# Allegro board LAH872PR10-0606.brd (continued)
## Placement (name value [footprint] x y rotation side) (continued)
PL4  5A Z150 20M 1210_2P  [5A_Z150_1210_2P]  166.59 45.59 270 bottom
PL301  1.5UH_9A_20%_7X7X3_M  [L_7X7X3_M_2P]  50.77 102.01 270 bottom
PL311  -  [5A_Z80_0805_2P]  45.22 112.96 0 bottom
PL501  1.5UH_9A_20%_7X7X3_M  [L_7X7X3_M_2P]  41.63 101.51 270 bottom
PL511  5A Z150 20M 1210_2P  [5A_Z150_1210_2P]  35.98 114.06 270 bottom
PL1811  5A_Z80_0805_2P  [5A_Z80_0805_2P-NPM]  171.42 56.03 270 bottom
PL1812  1UH_6.6A_20%_5X5X3_M  [L_5X5X3_M_2P]  161.59 54.92 180 bottom
PLB01  4.7UH_5.5A_20%_7X7X3_M  [L_7X7X3_M_2P]  179.96 49.04 180 bottom
PLB02  5A Z150 20M 1210_2P  [5A_Z150_1210_2P]  182.36 55.31 0 bottom
PLH01  1UH_11A_20%_7X7X3_M  [L_7X7X3_M_2P]  158.47 60.82 90 bottom
PLH11  -  [5A_Z80_0805_2P]  163.83 71.82 270 bottom
PLM01  1UH_11A_20%_7X7X3_M  [L_7X7X3_M_2P]  63.53 92.47 90 bottom
PLM11  -  [5A_Z80_0805_2P]  60.33 106.48 0 bottom
PLZ01  HCB3225KF-151T50_2P  [5A_Z150_1210_2P]  158.68 121.68 0 bottom
PLZ02  0.22UH_24A_20%_ 7X7X4_M  [L_7X7X4_M_4P]  157.49 101.58 270 bottom
PLZ04  0.22UH_24A_20%_ 7X7X4_M  [L_7X7X4_M_4P]  148.39 124.78 180 bottom
PQ1  -  [FDV301N-G_SOT23-3]  74.93 147.11 270 top
PQ2  -  [MMST3904-7-F_SOT323-3]  79.53 143.23 0 top
PQ11  -  [2N7002KW_SOT323-3]  193.93 45.94 270 top
PQ12  -  [L2N7002DW1T1G_SC88-6]  174.69 54.41 90 top
PQ13  -  [2N7002KDW_SOT363-6]  174.12 58.8 0 top
PQ801  -  [2N7002KW_SOT323-3]  147.57 43.4 270 top
PQ900  L2N7002DW1T1G 2N SC88-6  [DMN65D8LDW-7_SOT363-6]  170.2 41.34 0 top
PQB03  -  [2N7002KW_SOT323-3]  185.55 66.61 90 top
PQB11  -  [EMB04N03H_EDFN5X6-8-5]  179.46 62.91 90 top
PQB12  -  [AON7506_DFN3X3-8-5]  181.49 64.49 270 top
PQB13  -  [AON7506_DFN3X3-8-5]  176.25 54.16 90 bottom
PQB25  AON7506_DFN33-8-5  [AON7702L_DFN8-5]  185.44 48.57 270 bottom
PQB26  AON7408L_DFN8-5  [AON7702L_DFN8-5]  182.57 50.28 90 bottom
PQB28  -  [LMUN5113T1G_SOT323-3]  190.08 54.8 0 top
PQB29  -  [LTC015EUBFS8TL_UMT3F]  192.13 57.53 180 top
PQB31  2N7002KW_SOT323-3  [DMN65D8LW-7_SOT323-3]  190.41 49.57 0 top
PQB32  -  [RUM002N02GT2L_VMT3]  200.26 55.62 0 top
PQB33  -  [RUM002N02GT2L_VMT3]  196.76 54.94 0 top
PQH01  -  [RUM002N02GT2L_VMT3]  165.9 69.52 180 top
PQM01  -  [AONH36334_DFN3X3A8-10]  61.63 101.26 90 bottom
PQZ01  -  [AON6380_DFN5X6-8-5]  154.97 104.4 180 bottom
PQZ02  AON6314_N_DFN56-8-5  [Q_N_DFN56-8-5]  157.26 109.92 0 bottom
PQZ03  AON6314_N_DFN56-8-5  [Q_N_DFN56-8-5]  161.07 109.92 180 top
PQZ04  -  [AON6380_DFN5X6-8-5]  151.24 122.8 90 bottom
PQZ05  AON6314_N_DFN56-8-5  [Q_N_DFN56-8-5]  148.31 114.48 180 bottom
PQZ06  AON6314_N_DFN56-8-5  [Q_N_DFN56-8-5]  150.34 113.03 90 top
PR1  33_0402_5%  [R_0402]  78.94 148.57 0 top
PR3  100K_0402_1%  [R_0402]  78.94 147.74 0 top
PR4  10K_0402_1%  [R_0402]  81.16 144.6 270 top
PR5  2.2K_0402_5%  [R_0402]  82.44 148.57 0 top
PR6  15K_0402_1%  [R_0402]  79.86 146.28 180 top
PR7  100K_0402_1%  [R_0402]  80.46 142.92 0 top
PR9  16.2K_0402_1%  [R_0402]  52.17 84.65 270 bottom
PR31  0_0402_5%  [R_0402]  175.52 56.73 90 top
PR32  3.3K_1206_5%  [R_1206]  177.44 61.12 270 top
PR33  10K_0402_1%  [R_0402]  170.91 55.32 270 top
PR34  1M_0402_1%  [R_0402]  172.93 61.53 0 top
PR35  0_0402_5%  [R_0402]  173.8 56.8 0 top
PR36  1M_0402_1%  [R_0402]  176.5 56.02 270 top
PR37  100_0402_5%  [R_0402]  163.36 40.01 270 top
PR38  1M_0402_1%  [R_0402]  174.58 61.53 0 top
PR39  200_0402_5%  [R_0402]  164.74 39.24 0 top
PR40  100K_0402_1%  [R_0402]  171.83 56.7 0 top
PR41  10K_0402_1%  [R_0402]  165.65 40.06 180 top
PR42  100_0402_5%  [R_0402]  160.5 40.01 270 top
PR43  100K_0402_1%  [R_0402]  196.82 46.34 90 top
PR44  1M_0402_1%  [R_0402]  175.68 54.15 90 top
PR45  1M_0402_1%  [R_0402]  174.71 57.63 180 top
PR301  0_0603_5%  [R0603_0OHM]  47.6 106.55 270 bottom
PR302  499K_0402_1%  [R_0402]  54.38 110.55 0 bottom
PR303  150K_0402_1%  [R_0402]  54.38 109.66 0 bottom
PR304  10K_0402_1%  [R_0402]  52.29 111.77 270 bottom
PR305  4.7_1206_5%  [R_1206]  49.44 102.55 0 top
PR306  1K_0402_5%  [R_0402]  55.42 106.74 180 bottom
PR501  0_0603_5%  [R0603_0OHM]  37.56 106.04 270 bottom
PR502  0_0402_5%  [R0402_0OHM]  44.29 107.83 270 top
PR503  0_0402_5%  [R0402_0OHM]  42.77 107.83 270 top
PR504  10K_0402_1%  [R_0402]  43.14 109.99 180 bottom
PR505  4.7_1206_5%  [R_1206]  39.34 105.66 270 top
PR506  2.2K_0402_5%  [R_0402]  45.18 107.83 270 top
PR507  0_0402_5%  [R0402_0OHM]  43.73 104.07 180 top
PR508  1M_0402_5%  [R_0402]  46.5 105.97 0 top
PR509  1K_0402_5%  [R_0402]  45.39 106.23 180 bottom
PR801  0_0402_5%  [R0402_0OHM]  150.99 41.71 180 top
PR802  1.33K_0402_1%  [R_0402]  149.64 45.86 270 bottom
PR803  1K_0402_1%  [R_0402]  150.53 44.9 270 bottom
PR901  0_0402_5%  [R_0402]  191.61 54.36 270 top
PR902  200K_0402_1%  [R_0402]  174.02 43.23 90 top
PR903  300K_0402_1%  [R_0402]  173.2 43.23 90 top
PR904  200K_0402_1%  [R_0402]  144.79 83.03 0 top
PR905  100K_0402_1%  [R_0402]  175.12 47.68 180 top
PR906  0_0402_5%  [R_0402]  168.98 48.88 90 top
PR907  237K_0402_1%  [R_0402]  169.83 49.79 270 top
PR908  43.2K_0402_1%  [R_0402]  170.66 49.79 270 top
PR909  14.7K_0402_1%  [R_0402]  173.88 49.46 0 top
PR911  4.32K_0402_1%  [R_0402]  173.07 48.62 90 top
PR1801  0_0402_5%  [R0402_0OHM]  165.02 59.11 180 bottom
PR1802  1M_0402_5%  [R_0402]  164.11 58.35 0 bottom
PR1803  100K_0402_5%  [R_0402]  162.78 58.36 270 bottom
PR1804  4.7_1206_5%  [R_1206]  161.83 55.05 270 top
PR1805  10K_0402_1%  [R_0402]  167.81 57.46 180 bottom
PR1806  20K_0402_1%  [R_0402]  166.9 59.11 0 bottom
PR2501  0_0402_5%  [R0402_0OHM]  59.6 82.69 270 bottom
PR2502  21.5K_0402_1%  [R_0402]  62.21 71.81 180 bottom
PR2503  10K_0402_1%  [R_0402]  61.3 70.92 0 bottom
PR2504  2.2_0402_1%  [R_0402]  65.31 77.71 90 bottom
PRB01  0.01_1206_1%  [R_1206_4P-D]  170.77 50.19 270 bottom
PRB02  0.01_1206_1%  [R_1206_4P-D]  183.1 60.93 270 top
PRB03  3M_0402_5%  [R_0402]  182.6 65.9 90 top
PRB04  1M_0402_1%  [R_0402]  182.6 67.55 90 top
PRB07  4.02K_0402_1%  [R_0402]  192.05 44.36 90 bottom
PRB08  4.02K_0402_1%  [R_0402]  181.83 65.9 90 top
PRB09  374K_0402_1%  [R_0402]  190.71 52.51 0 top
PRB10  52.3K_0402_1%  [R_0402]  191.63 51.62 180 top
PRB11  1_0402_5%  [R_0402]  189.7 52.64 0 bottom
PRB12  2_0402_5%  [R_0402]  189.7 51.75 0 bottom
PRB13  100K_0402_5%  [R_0402]  190.51 49.97 0 bottom
PRB14  0_0603_1%  [R0603_0OHM]  191.21 48.85 180 bottom
PRB15  10_1206_1%  [R_1206]  187.42 54.45 0 bottom
PRB16  47K_0402_1%  [R_0402]  195.46 53.91 90 bottom
PRB17  150K_0402_1%  [R_0402]  194.67 54.95 270 bottom
PRB18  200K_0402_1%  [R_0402]  195.49 53.78 180 top
PRB19  0_0402_5%  [R0402_0OHM]  196.25 54.95 270 bottom
PRB20  0_0402_5%  [R0402_0OHM]  197.04 54.95 270 bottom
PRB21  0_0402_5%  [R0402_0OHM]  197.85 54.69 270 bottom
PRB22  0_0402_5%  [R0402_0OHM]  198.66 53.78 90 bottom
PRB23  100K_0402_1%  [R_0402]  198.97 52.64 0 bottom
PRB24  100K_0402_1%  [R_0402]  198.97 51.77 0 top
PRB25  499K_0402_1%  [R_0402]  193.87 53.91 90 bottom
PRB26  768K_0402_1%  [R_0402]  193.89 55.53 90 bottom
PRB27  200K_0402_1%  [R_0402]  193.76 54.75 270 top
PRB28  100K_0402_1%  [R_0402]  199.88 50.86 180 top
PRB29  0_0402_5%  [R0402_0OHM]  199.88 50.83 180 bottom
PRB30  100_0402_5%  [R_0402]  198.94 49.08 90 top
PRB31  0_0402_5%  [R0402_0OHM]  199.88 49.04 180 bottom
PRB35  100_0402_5%  [R_0402]  199.88 47.3 180 bottom
PRB36  2_0402_5%  [R_0402]  196.76 44.01 270 bottom
PRB37  0_0402_5%  [R0402_0OHM]  197.58 44.01 270 bottom
PRB38  22.6K_0402_1%  [R_0402]  195.25 45.22 270 bottom
PRB39  4.7_0402_5%  [R_0402]  191.22 45.3 270 bottom
PRB40  4.7_1206_5%  [R_1206]  182.61 49.93 270 top
PRB41  0_0603_5%  [R_0603]  188.2 56.85 270 top
PRB42  10K_0402_5%  [R_0402]  198.87 55.79 180 top
PRB43  160K_0402_1%  [R_0402]  198.03 54.67 270 top
PRB44  10K_0402_5%  [R_0402]  194.57 54.67 0 top
PRB45  100K_0402_1%  [R_0402]  189.75 46.59 0 top
PRH01  0_0402_5%  [R0402_0OHM]  165.58 67.66 270 top
PRH02  1M_0402_1%  [R_0402]  166.55 66.74 90 top
PRH03  0_0402_5%  [R_0402]  166.7 59.94 90 bottom
PRH04  0_0402_5%  [R_0402]  167.53 60.85 270 bottom
PRH05  100K_0402_5%  [R_0402]  166.73 63.42 90 top
PRH06  10_0402_1%  [R_0402]  165.55 60.83 180 bottom
PRH07  4.7_1206_5%  [R_1206]  159.76 62.24 90 top
PRH08  5.9K_0402_1%  [R_0402]  167.53 64.18 0 bottom
PRH09  10K_0402_1%  [R_0402]  167.53 63.39 0 bottom
PRH11  2.2_0402_1%  [R_0402]  168.46 61.63 180 bottom
PRH12  1K_0402_1%  [R_0402]  168.44 64.99 180 bottom
PRH13  10_0402_5%  [R_0402]  168.49 65.69 0 top
PRH14  0_0402_5%  [R0402_0OHM]  168.49 64.86 0 top
PRH15  0_0402_5%  [R0402_0OHM]  168.49 64.04 0 top
PRH20  0_0402_5%  [R0402_0OHM]  165.41 71.52 180 top
PRM01  4.7_1206_5%  [R_1206]  63.41 99.82 90 top
PRM02  2.2_0603_5%  [R_0603]  63.15 109.72 270 bottom
PRM03  5K_0402_1%  [R_0402]  67 110.7 0 bottom
PRM04  5.1_0603_5%  [R_0603]  68.22 113.85 180 bottom
PRM05  2.2_0603_5%  [R_0603]  66.82 112.64 0 bottom
PRM06  10K_0402_1%  [R_0402]  65.88 116.98 270 bottom
PRM07  453K_0402_1%  [R_0402]  64.97 116.98 270 bottom
PRM08  0_0402_5%  [R0402_0OHM]  64.16 116.98 270 bottom
PRM09  0_0402_5%  [R0402_0OHM]  61.4 116.98 270 bottom
PRM10  6.04K_0402_1%  [R_0402]  59.93 115.31 180 bottom
PRM11  10K_0402_1%  [R_0402]  59.93 116.96 180 bottom
PRM13  0_0402_5%  [R_0402]  58.14 113.65 90 bottom
PRM14  0_0402_5%  [R0402_0OHM]  59.01 113.66 0 bottom
PRZ00  2K_0402_1%  [R_0402]  156.72 141.97 180 top
PRZ02  10_0402_5%  [R_0402]  155.86 144.57 180 top
PRZ03  2.37K_0402_1%  [R_0402]  154.94 143.71 0 top
PRZ04  47K_0402_1%  [R_0402]  155.8 141.13 270 top
PRZ05  34K_0402_1%  [R_0402]  154.07 141.14 270 top
PRZ06  0_0402_5%  [R0402_0OHM]  154.1 143.71 270 top
PRZ07  301_0402_1%  [R_0402]  154.12 141.98 180 top
PRZ08  2.2_0603_5%  [R_0603]  152.05 137.13 0 top
PRZ09  2.61K_0402_1%  [R_0402]  159.43 139.57 180 top
PRZ10  4.7_1206_5%  [R_1206]  155.1 105.02 90 top
PRZ11  11K_0402_1%  [R_0402]  159.43 140.39 180 top
PRZ12  3.65K_0603_1%  [R_0603]  159.23 138.62 270 top
PRZ13  475_0402_1%  [R_0402]  157.64 143.3 90 top
PRZ15  100_0402_1%  [R_0402]  158.58 143.38 0 top
PRZ16  13.3K_0402_1%  [R_0402]  151.55 144.98 270 top
PRZ18  133K_0402_1%  [R_0402]  150.72 145.04 270 top
PRZ21  100K_0402_1%  [R_0402]  149.07 145.3 270 top
PRZ23  2.2_0402_1%  [R_0402]  148.24 145.61 270 top
PRZ26  1_0603_5%  [R_0603]  148.62 135.31 0 top
PRZ47  2.74K_0402_1%  [R_0402]  142.76 138.07 0 top
PRZ51  10_0402_5%  [R_0402]  139.97 138.89 270 top
PRZ65  2K_0402_1%  [R_0402]  141.04 136.26 90 top
PRZ66  549_0402_1%  [R_0402]  143.46 141.08 270 top
PRZ67  10_0402_5%  [R_0402]  140.36 139.7 0 top
PRZ69  0_0402_5%  [R0402_0OHM]  139.61 140.6 270 top
PRZ70  100K_0402_5%  [R_0402]  143.61 137.55 270 bottom
PRZ71  11K_0402_1%  [R_0402]  141.64 144.66 270 top
PRZ72  100_0402_1%  [R_0402]  143.47 141.92 180 top
PRZ73  301_0402_1%  [R_0402]  141.9 137.17 270 top
PRZ74  4.7_1206_5%  [R_1206]  147.35 119.25 0 top
PRZ75  0_0402_5%  [R0402_0OHM]  140.75 137.97 90 top
PRZ76  133K_0402_1%  [R_0402]  145.58 144.98 270 top
PRZ77  54.9K_0402_1%  [R_0402]  141.01 135.4 0 top
PRZ78  210K_0402_1%  [R_0402]  143.7 135.33 180 top
PRZ79  2.61K_0402_1%  [R_0402]  140.88 144.66 270 top
PRZ80  13.3K_0402_1%  [R_0402]  142.9 143.51 0 top
PRZ81  10K_0402_1%  [R_0402]  142.77 142.74 0 top
PRZ82  2.2_0603_5%  [R_0603]  145.7 136.2 270 top
PRZ84  3.65K_0603_1%  [R_0603]  139.86 144.71 270 top
PRZ85  0_0402_5%  [R_0402]  74.32 130.04 0 top
PRZ86  150K_0402_1%  [R_0402]  152.37 144.06 90 top
PRZ87  150K_0402_1%  [R_0402]  143.81 144.27 180 top
PU301  -  [SY8286BRAC_QFN20_3X3]  49.35 106.73 0 bottom
PU501  -  [SY8288CRAC_QFN20_3X3]  39.31 106.22 0 bottom
PU800  -  [APL5336KAI-TRL_SOP8P8]  147.96 45.76 270 bottom
PU900  -  [AZV3002RL-7_U-FLGA8_1P65X1P65]  171.82 46.18 0 top
PU1801  -  [RT8061AZQW_WDFN10_3X3]  164.24 54.38 90 bottom
PU2501  -  [RT9059GSP_SO8]  59.98 79.85 0 bottom
PUB01  -  [ISL95522HRZ-T_TQFN32_4X4]  196.7 47.8 90 bottom
PUH01  -  [RT6226AGQUF_UQFN12_3X3]  165.1 62.13 90 bottom
PUM01  -  [RT8207PGQW_WQFN20_3X3]  62.05 112.1 90 bottom
PUZ01  ISL62771HRTZ-T_TQFN40_5X5  [ISL62771HRTZ-T_TQFN40_5X5-S]  149.92 142.63 180 top
Q1  L2N7002DW1T1G_SC88-6  [DMN66D0LDW-7_SOT363-6]  126.52 56.6 90 bottom
Q2  AO3416L_SOT23-3  [AO3416_SOT23-3]  133.51 34.25 0 bottom
Q3  ME2301DC-G 1P SOT23-3  [2N7002K_SOT23-3]  109.51 40.85 180 bottom
Q4  AO3416L_SOT23-3  [AO3416_SOT23-3]  104.87 34.96 180 bottom
Q5  L2N7002DW1T1G_SC88-6  [DMN66D0LDW-7_SOT363-6]  114.26 34.76 270 bottom
Q6  -  [2N7002K_SOT23-3]  109.51 35.77 180 bottom
Q7  L2N7002DW1T1G  [DMN66D0LDW-7_SOT363-6]  17.87 122.76 270 bottom
Q8  DDTA144VCA-7-F-GP  [2N7002K_SOT23-3]  11.57 121.22 90 bottom
Q9  DDTA144VCA-7-F-GP  [2N7002K_SOT23-3]  11.57 117.15 90 bottom
Q10  -  [LN2306LT1G_SOT23-3]  54.24 32.95 270 top
Q11  DDTA144VCA-7-F-GP  [2N7002K_SOT23-3]  56.96 29.01 90 top
Q12  -  [2N7002KW_SOT323-3]  20.23 123.28 0 bottom
Q13  -  [LMBT3904LT1G_SOT23-3]  101.89 125.95 180 bottom
Q14  L2N7002DW1T1G  [DMN66D0LDW-7_SOT363-6]  17.87 120.22 270 bottom
Q15  L2N7002DW1T1G_SC88-6  [DMN66D0LDW-7_SOT363-6]  120.28 38.52 270 bottom
Q16  -  [2N7002K_SOT23-3]  152.56 56.98 180 top
Q17  -  [2N7002K_SOT23-3]  148.5 56.98 180 top
Q18  AO3416L_SOT23-3  [AO3416_SOT23-3]  131.09 42.46 270 bottom
Q19  AO3416L_SOT23-3  [AO3416_SOT23-3]  135.79 42.46 270 bottom
Q20  AO3416L_SOT23-3  [AO3416_SOT23-3]  131.07 38.44 270 bottom
Q21  AO3416L_SOT23-3  [AO3416_SOT23-3]  135.71 38.44 270 bottom
QA2  -  [LN2306LT1G_SOT23-3]  41.42 24.61 90 top
QC1  BSS138W 1N SOT-323-3  [MESS138W-G_SOT323-3]  122.14 101.72 0 top
QC2  ME2N7002F1KW-G 2N SOT-363-6  [DMN66D0LDW-7_SOT363-6]  59.84 77.09 0 top
QC3  -  [2N7002K_SOT23-3]  149.61 82.1 270 top
QE1  -  [2N7002K_SOT23-3]  36.27 62.03 270 top
QS1  L2N7002DW1T1G  [DMN66D0LDW-7_SOT363-6]  106.08 42.11 270 bottom
QV1  -  [2N7002K_SOT23-3]  28.36 105.24 0 bottom
QV2  -  [MMBT3904_NL_SOT23-3]  29.88 96.55 180 bottom
QV3  L2N7002DW1T1G  [DMN66D0LDW-7_SOT363-6]  26 99.01 270 bottom
R1  4.7K_0402_5%  [R_0402]  128.88 55.6 180 bottom
R2  2.2K_0402_5%  [R_0402]  126.84 58.6 270 top
R3  2.2K_0402_5%  [R_0402]  124.64 60.76 90 bottom
R4  4.7K_0402_5%  [R_0402]  126.13 55.6 0 bottom
R5  0_0201_5%  [R_0201]  211.39 42.03 0 top
R6  33_0402_5%  [R_0402]  42.58 82.47 90 bottom
R7  0_0603_5%  [R_0603]  215.43 46.99 90 top
R8  0_0402_5%  [R_0402-NPM]  206.08 46.86 0 bottom
R9  0_0402_5%  [R_0402-NPM]  206.08 47.62 0 bottom
R11  0_0201_5%  [R_0201]  208.95 46.9 270 top
R12  0_0201_5%  [R_0201]  209.58 46.9 270 top
R13  0_0603_5%  [R_0603]  218.6 48.38 270 top
R14  0_0603_5%  [R0603_0OHM]  218.6 44.57 90 top
R17  10K_0402_5%  [R_0402]  207.36 48.18 90 top
R19  10K_0402_5%  [R_0402]  206.16 48.18 90 top
R20  0_0603_5%  [R_0603]  219.93 44.64 0 top
R21  4.7K_0402_5%  [R_0402]  115.54 32.84 270 bottom
R22  0_0402_5%  [R_0402]  131.16 33.66 270 bottom
R23  100K_0402_5%  [R_0402]  129.51 33.66 270 bottom
R24  0_0402_5%  [R0402_0OHM]  135.92 34.43 270 bottom
R25  4.7K_0402_5%  [R_0402]  125 33.54 270 bottom
R26  4.7K_0402_5%  [R_0402]  124.11 33.54 270 bottom
R27  0_0603_5%  [R_0603]  112.49 39.86 180 bottom
R28  0_0402_5%  [R_0402]  108.73 44.57 0 bottom
R29  2.2K_0402_5%  [R_0402]  130.34 32.75 90 bottom
R30  51K_0402_5%  [R_0402]  100.49 36.58 270 bottom
R31  100K_0402_5%  [R_0402]  101.38 36.58 270 bottom
R32  100_0603_1%  [R_0603]  111.13 34.92 270 bottom
R33  10K_0402_5%  [R_0402]  113.75 31.94 0 bottom
R34  20K_0402_1%  [R_0402]  54.17 77.3 0 top
R35  10K_0402_5%  [R_0402]  112.95 31.94 180 bottom
R36  0_0402_5%  [R0402_0OHM]  59.72 28.68 90 top
R37  100K_0402_5%  [R_0402]  58.07 31.61 90 top
R38  1K_0402_5%  [R_0402]  60.61 29.6 270 top
R39  0_0402_5%  [R0402_0OHM]  58.07 33.38 90 top
R40  200_0402_5%  [R_0402]  10.94 119.95 0 top
R41  0_0402_5%  [R_0402]  58.96 34.3 270 top
R42  10K_0402_5%  [R_0402]  23.08 123.01 270 bottom
R43  200_0402_5%  [R_0402]  10.94 122.42 0 top
R44  0_0402_5%  [R0402_0OHM]  19.59 120.15 270 bottom
R45  18.7K_0402_1%  [R_0402]  181.09 66.54 180 bottom
R46  2K_0402_1%  [R_0402]  176.75 68.02 270 bottom
R47  0_0603_5%  [R0603_0OHM]  218.98 27.74 180 top
R48  0_0603_5%  [R_0603]  215.17 27.74 0 top
R49  100K_0402_5%  [R_0402]  17.48 117.79 0 bottom
R50  100K_0402_5%  [R_0402]  16.68 117.79 180 bottom
R51  0_0402_5%  [R_0402]  33.09 61.68 270 top
R52  20K_0402_5%  [R_0402]  154.14 44.25 0 top
R53  0_0402_5%  [R_0402]  32.33 61.68 270 top
R54  1K_0402_5%  [R_0402]  142.6 40.44 180 bottom
R55  100K_0402_5%  [R_0402]  121.26 37.62 0 bottom
R56  470_0603_5%  [R_0603]  154.21 59.18 270 top
R57  100K_0402_5%  [R_0402]  117.3 37.01 180 bottom
R58  4.7K_0402_5%  [R_0402]  147.66 58.73 0 top
R59  1K_0402_5%  [R_0402]  133.63 35.9 0 bottom
R60  100K_0402_5%  [R_0402]  122.18 38.53 180 bottom
R61  0_0402_5%  [R0402_0OHM]  124.09 36.62 270 bottom
R63  10K_0402_5%  [R_0402]  115.57 37.87 270 bottom
R64  0_0402_5%  [R_0402]  125.54 43.19 270 bottom
R65  0_0402_5%  [R0402_0OHM]  116.38 37.87 0 bottom
R66  0_0201_5%  [R_0201]  126.72 36.36 0 bottom
R67  0_0201_5%  [R_0201]  126.05 36.35 270 bottom
R68  0_0402_5%  [R_0402]  126.37 43.19 270 bottom
R71  0_0402_5%  [R_0402]  131.8 44.77 270 bottom
R72  0_0402_5%  [R_0402]  131.62 35.14 90 bottom
R73  0_0402_5%  [R_0402]  140.12 37.83 90 bottom
R78  100K_0402_5%  [R_0402]  19.27 123.76 180 bottom
RA1  0_0805_5%  [R0805_0OHM]  37.65 7.23 180 top
RA8  100K_0402_5%  [R_0402]  35.42 9.14 180 top
RA30  0_0402_5%  [R_0402]  36.43 13.65 180 top
RA31  1K_0402_5%  [R_0402]  36.43 17.97 180 top
RA32  0_0402_5%  [R_0402]  36.43 16.44 180 top
RA33  0_0402_5%  [R0402_0OHM]  39.02 8.56 90 top
RA34  0_0603_5%  [R0603_0OHM]  26.83 20.12 90 top
RA35  0_0402_5%  [R0402_0OHM]  34.72 20.57 180 top
RA36  0_0402_5%  [R0402_0OHM]  36.41 20 0 top
RA37  0_0402_5%  [R0402_0OHM]  30.51 20.43 90 top
RA38  0_0402_5%  [R_0402]  21.69 9.22 270 top
RA39  0_0402_5%  [R_0402]  26.96 8.01 270 top
RA40  100K_0402_5%  [R_0402]  33.74 17.97 0 top
RA41  0_0402_5%  [R_0402]  29.69 20.43 90 top
RA46  33_0402_5%  [R_0402]  36.75 10.41 180 top
RA47  100K_0402_5%  [R_0402]  26.12 16.82 0 top
RA48  10K_0402_5%  [R_0402]  35.52 17.2 0 top
RA50  33_0402_5%  [R_0402]  37.7 12.19 180 top
RA51  200K_0402_1%  [R_0402]  32.91 19.74 0 top
RA52  4.7K_0402_5%  [R_0402]  21.8 13.77 0 top
RA53  4.7K_0402_5%  [R_0402]  21.8 12.25 0 top
RA54  10K_0402_5%  [R_0402]  17.18 11.98 90 bottom
RA55  1K_0402_5%  [R_0402]  23.96 13.56 0 top
RA56  2.2K_0402_5%  [R_0402]  19.41 13.97 180 top
RA57  10K_0402_5%  [R_0402]  18.13 10.35 270 bottom
RA58  10_0402_1%  [R_0402]  24.88 14.89 180 top
RA59  1K_0402_5%  [R_0402]  23.96 15.67 0 top
RA60  2.2K_0402_5%  [R_0402]  20.35 13.98 90 top
RA61  10_0402_1%  [R_0402]  24.88 12.8 180 top
RA62  0_0402_5%  [R0402_0OHM]  16.09 15.55 0 top
RA63  0_0805_5%  [R_0805]  23.97 19.08 90 top
RA65  0_0402_5%  [R0402_0OHM]  39.16 15.3 180 top
RC1  196_0402_1%  [R_0402]  145.71 81.26 180 top
RC2  196_0402_1%  [R_0402]  144.79 79.29 0 top
RC3  0_0402_5%  [R0402_0OHM]  105.11 79.88 0 top
RC4  39.2_0402_1%  [R_0402]  106.01 79.05 270 top
RC5  1K_0402_1%  [R_0402]  105.12 79.05 270 top
RC6  1K_0402_5%  [R_0402]  106.08 81.67 270 top
RC7  1K_0402_1%  [R_0402]  103.28 80.76 270 top
RC8  2.2K_0402_5%  [R_0402]  123.8 101.14 90 top
RC9  0_0402_5%  [R0402_0OHM]  138.67 143 180 top
RC10  0_0402_5%  [R0402_0OHM]  123.73 92.25 270 top
RC11  1K_0402_5%  [R_0402]  115.03 140.44 90 top
RC12  0_0402_5%  [R0402_0OHM]  122.71 92.25 270 top
RC13  150_0402_1%  [R_0402]  125.64 90.15 180 top
RC14  1K_0402_5%  [R_0402]  116.68 140.44 90 top
RC15  2K_0402_1%  [R_0402]  125.64 90.97 180 top
RC16  1K_0402_5%  [R_0402]  115.86 140.44 90 top
RC17  300_0402_5%  [R_0402]  118.39 97.84 270 top
RC18  300_0402_5%  [R_0402]  119.72 94.15 90 top
RC19  4.7K_0402_5%  [R_0402]  124.36 105.5 90 top
RC20  4.7K_0402_5%  [R_0402]  123.47 105.5 90 top
RC21  0_0402_5%  [R0402_0OHM]  124.36 103.79 90 top
RC22  100K_0402_5%  [R_0402]  152.36 81.08 0 bottom
RC23  0_0402_5%  [R_0402]  123.47 104.7 270 top
RC24  1K_0402_5%  [R_0402]  123.73 92.99 90 top
RC25  1K_0402_5%  [R_0402]  119.88 92.38 90 top
RC26  4.7K_0402_5%  [R_0402]  131.99 39.19 90 top
RC27  1K_0402_5%  [R_0402]  119.88 91.26 270 top
RC28  1K_0402_5%  [R_0402]  124.19 88.77 180 top
RC29  0_0402_5%  [R0402_0OHM]  118.99 90.35 90 top
RC30  0_0402_5%  [R_0402]  118.03 90.35 90 top
RC31  0_0402_5%  [R_0402]  124.07 74.43 270 top
RC32  0_0402_5%  [R_0402]  131.98 40.91 90 top
RC33  1K_0402_5%  [R_0402]  119.05 97.99 270 bottom
RC34  10K_0402_5%  [R_0402]  144.53 71.67 0 bottom
RC35  10K_0402_5%  [R_0402]  120.54 58.59 0 top
RC36  10K_0402_5%  [R_0402]  104.76 57.06 180 top
RC37  0_0402_5%  [R_0402]  131.66 61.39 270 bottom
RC38  0_0402_5%  [R_0402]  47.07 29.81 180 bottom
RC39  0_0402_5%  [R0402_0OHM]  30.37 69.92 90 top
RC40  0_0402_5%  [R0402_0OHM]  33.69 68.5 90 top
RC41  15K_0402_5%  [R_0402]  143.19 77.21 180 bottom
RC42  10K_0402_5%  [R_0402]  151.55 81.01 90 bottom
RC43  15K_0402_5%  [R_0402]  143.19 78.23 180 bottom
RC44  10K_0402_5%  [R_0402]  43.01 86.97 270 top
RC45  15K_0402_5%  [R_0402]  142.21 74.67 270 bottom
RC48  4.7K_0402_5%  [R_0402]  148.25 79.22 180 bottom
RC49  100K_0402_5%  [R_0402]  143.18 79.03 180 bottom
RC50  0_0402_5%  [R_0402]  147.08 69.57 0 top
RC51  0_0402_5%  [R_0402]  144.5 72.71 0 bottom
RC52  0_0402_5%  [R0402_0OHM]  152.36 81.85 0 bottom
RC53  10K_0402_5%  [R_0402]  119.81 60.76 90 bottom
RC54  0_0402_5%  [R0402_0OHM]  46.15 28.93 0 bottom
RC55  10K_0402_5%  [R_0402]  147.02 72.43 0 top
RC56  10K_0402_5%  [R_0402]  120.83 61.67 270 bottom
RC57  10K_0402_5%  [R_0402]  118.76 57.76 0 top
RC59  10K_0402_5%  [R_0402]  104.16 47.11 0 top
RC60  10K_0402_5%  [R_0402]  144.79 72.43 0 top
RC61  10K_0402_5%  [R_0402]  120.95 63.8 90 bottom
RC62  22 +-5% 0402  [R_0402]  147.99 71.38 270 top
RC63  33_0402_5%  [R_0402]  144.85 78.21 0 top
RC65  8.2K_0402_5%  [R_0402]  99.25 43.76 180 top
RC66  0_0402_5%  [R_0402]  100.3 47.1 90 top
RC67  0_0402_5%  [R0402_0OHM]  100.3 45.19 90 top
RC68  100K_0402_5%  [R_0402]  150.78 81.01 90 bottom
RC69  100K_0402_5%  [R_0402]  145.41 75.94 180 bottom
RC70  10K_0402_5%  [R_0402]  145.79 77.06 180 top
RC71  1K_0402_5%  [R_0402]  145.41 78.23 180 bottom
RC72  2.2K_0402_5%  [R_0402]  145.41 77.21 180 bottom
RC73  2.2K_0402_5%  [R_0402]  145.41 73.72 180 bottom
RC74  10K_0402_5%  [R_0402]  148.25 80.05 180 bottom
RC75  10K_0402_5%  [R_0402]  119.37 74.24 270 top
RC76  10K_0402_5%  [R_0402]  121.06 49.71 270 bottom
RC77  10K_0402_5%  [R_0402]  118.7 51.86 0 bottom
RC78  10K_0402_5%  [R_0402]  118.58 49.71 270 bottom
RC79  10K_0402_5%  [R_0402]  144.81 74.4 0 top
RC80  10K_0402_5%  [R_0402]  144.79 71.35 0 top
RC81  10K_0402_5%  [R_0402]  140.84 77.21 180 bottom
RC82  10K_0402_5%  [R_0402]  144.81 73.45 0 top
RC83  10K_0402_5%  [R_0402]  145.16 61.26 180 bottom
RC84  10K_0402_5%  [R_0402]  119.67 57 180 top
RC85  10K_0402_5%  [R_0402]  133.43 67.39 270 top
RC86  10K_0402_5%  [R_0402]  145.16 60.32 180 bottom
RC87  10K_0402_5%  [R_0402]  132.61 67.39 270 top
RC88  2K_0402_5%  [R_0402]  120.23 48.79 90 bottom
RC89  2K_0402_5%  [R_0402]  120.93 51.86 270 bottom
RC90  2K_0402_5%  [R_0402]  147.04 74.42 0 top
RC91  2K_0402_5%  [R_0402]  147.09 71.36 270 top
RC92  2.2K_0402_5%  [R_0402]  143.19 75.94 180 bottom
RC93  0_0402_5%  [R0402_0OHM]  157.21 75.37 180 bottom
RC94  2K_0402_5%  [R_0402]  119.41 48.79 90 bottom
RC95  2.2K_0402_5%  [R_0402]  147.04 73.4 0 top
RC96  22K_0402_5%  [R_0402]  144.85 75.92 0 top
RC97  20M_0402_5%  [R_0402]  145.21 64.97 270 bottom
RC98  10K_0402_5%  [R_0402]  148.25 81.13 180 bottom
RC99  10K_0402_5%  [R_0402]  103.85 57.95 0 top
RC100  11.8K_0402_1%  [R_0402]  132.89 73.34 180 top
RC101  10K_0402_5%  [R_0402]  121.45 59.41 180 top
RC102  1K_0402_1%  [R_0402]  129.98 71.82 225 top
RC103  1K_0402_1%  [R_0402]  130.05 72.83 180 top
RC104  10K_0402_5%  [R_0402]  121.34 64.94 180 top
RC105  1K_0402_1%  [R_0402]  144.79 80.24 0 top
RC106  1K_0402_1%  [R_0402]  144.79 82.14 0 top
RC107  33_0402_5%  [R_0402]  122.9 60.28 90 bottom
RC108  10K_0402_5%  [R_0402]  145.72 80.24 180 bottom
RC109  33_0402_5%  [R_0402]  123.73 60.28 90 bottom
RC110  33_0402_5%  [R_0402]  130.84 60.48 90 bottom
RC111  33_0402_5%  [R_0402]  101.25 48.03 270 top
RC112  100K_0402_5%  [R_0402]  99.16 49.79 270 top
RC113  10K_0402_5%  [R_0402]  32.22 81.47 0 top
RC114  10K_0402_5%  [R_0402]  129.25 60.31 270 bottom
RC115  10K_0402_5%  [R_0402]  126.39 62.47 270 bottom
RC116  1M_0402_5%  [R_0402]  141.11 88.8 90 bottom
RC117  0_0603_5%  [R_0603]  131.66 62.33 180 top
RC118  0_0603_5%  [R0603_0OHM]  128.81 63.6 0 top
RC119  10K_0402_5%  [R_0402]  131.92 48.63 270 bottom
RC120  10K_0402_5%  [R_0402]  128.35 62.21 0 top
RC121  10K_0402_5%  [R_0402]  129.25 60.48 90 top
RC122  0_0402_5%  [R0402_0OHM]  122.77 64.97 90 top
RC123  0_0402_5%  [R0402_0OHM]  133.99 60.53 90 top
RC124  1K_0402_5%  [R_0402]  148.49 62.16 270 top
RC125  1K_0402_5%  [R_0402]  204.83 37.78 180 top
RC126  10M_0402_5%  [R_0402]  153.45 80.75 90 top
RC127  0_0402_5%  [R_0402]  156.29 74.48 0 bottom
RC128  10_0402_5%  [R_0402]  131.85 50.98 270 bottom
RC130  10K_0402_5%  [R_0402]  31.9 85.28 0 top
RC131  10K_0402_5%  [R_0402]  25.62 90.94 270 top
RC132  10K_0402_5%  [R_0402]  156.23 78.04 0 bottom
RC133  10K_0402_5%  [R_0402]  157.15 78.99 180 bottom
RD1  1K_0402_1%  [R_0402]  71.39 83.66 180 top
RD2  1K_0402_1%  [R_0402]  71.45 69.57 180 top
RD3  1K_0402_1%  [R_0402]  70.54 68.74 0 top
RD4  0_0402_5%  [R0402_0OHM]  79.58 76.74 180 top
RD5  1K_0402_1%  [R_0402]  74.39 47.32 270 top
RD6  1K_0402_1%  [R_0402]  75.35 46.4 90 top
RE2  0_0603_5%  [R_0603]  43.21 89.4 270 top
RE3  0_0603_5%  [R_0603]  29.05 76.39 0 top
RE5  100K_0402_1%  [R_0402]  54.29 69.35 0 top
RE6  0_0402_5%  [R0402_0OHM]  43.77 86.97 270 top
RE7  0_0603_5%  [R_0603]  29.05 72.96 0 top
RE8  0_0603_5%  [R0603_0OHM]  32.99 72.9 180 top
RE9  0_0402_1%  [R_0402]  55.2 68.33 180 top
RE10  2.2K_0402_5%  [R_0402]  57.9 79.88 180 top
RE11  33_0402_5%  [R_0402]  33.13 77.15 180 top
RE12  0_0402_5%  [R_0402]  41.64 66.04 180 top
RE13  2.2K_0402_5%  [R_0402]  55.02 74.45 180 top
RE14  2.2K_0402_5%  [R_0402]  55.02 75.27 180 top
RE15  2.2K_0402_5%  [R_0402]  56.88 75.94 180 top
RE16  100K_0402_5%  [R_0402]  201.85 43.24 180 bottom
RE17  10K_0402_5%  [R_0402]  32.8 71.21 180 top
RE18  100K_0402_5%  [R_0402]  42.25 86.05 90 top
RE19  10K_0402_5%  [R_0402]  31.96 75.12 0 top
RE20  0_0402_5%  [R0402_0OHM]  52.6 86.16 90 top
RE21  10K_0402_5%  [R_0402]  31.96 74.33 0 top
RE23  10K_0402_5%  [R_0402]  42.08 81.02 180 bottom
RE24  10K_0402_5%  [R_0402]  54.59 84.64 180 top
RE25  10K_0402_5%  [R_0402]  55.69 80.48 90 top
RE26  100K_0402_5%  [R_0402]  136.75 34.43 270 bottom
RE28  100K_0402_5%  [R_0402]  50.94 86.16 90 top
RE29  100K_0402_5%  [R_0402]  38.32 67.29 90 bottom
RE30  0_0402_5%  [R0402_0OHM]  47.28 86.09 90 top
RE31  0_0402_5%  [R0402_0OHM]  32.22 79.81 0 top
RE32  0_0402_5%  [R0402_0OHM]  32.8 70.32 180 top
RE33  0_0402_5%  [R0402_0OHM]  48.22 88.32 0 top
RE34  0_0402_5%  [R_0402]  40.29 88.53 270 top
RE35  0_0402_5%  [R0402_0OHM]  40.12 83.24 180 bottom
RE36  0_0402_5%  [R_0402]  36.28 81.02 270 bottom
RE37  0_0402_5%  [R0402_0OHM]  44.74 88.37 90 top
RE38  100K_0402_5%  [R_0402]  32.8 69.43 180 top
RE39  10K_0402_5%  [R_0402]  53.91 71.08 0 top
RE41  6.8K_0402_5%  [R_0402]  54.82 71.89 180 top
RE43  240_0402_1%  [R_0402]  58.82 36 0 bottom
RE44  100K_0402_5%  [R_0402]  222.87 64.75 180 top
RE47  100K_0402_5%  [R_0402]  29.55 75.12 0 top
RE48  0_0402_5%  [R0402_0OHM]  56.1 72.4 270 top
RE49  100K_0402_5%  [R_0402]  43.16 27.74 180 bottom
RE50  47K_0402_5%  [R_0402]  38.12 65.91 0 top
RE51  10K_0402_5%  [R_0402]  35.07 72.39 0 bottom
RE52  10K_0402_5%  [R_0402]  35.07 71.56 0 bottom
RE53  0_0402_5%  [R_0402]  54.69 80.49 90 top
RE54  100K_0402_5%  [R_0402]  56.71 79.88 0 bottom
RH1  33_0402_5%  [R_0402]  91.16 135.07 270 bottom
RH2  10K_0402_5%  [R_0402]  92.25 135.03 270 bottom
RH3  10K_0402_5%  [R_0402]  93.14 135.03 270 bottom
RH4  10K_0402_5%  [R_0402]  95.04 134.23 180 bottom
RH5  33_0402_5%  [R_0402]  94.08 124.66 270 bottom
RL1  0_0603_5%  [R_0603]  19.47 90.42 90 top
RL2  33_0402_5%  [R_0402]  19.2 86.76 0 top
RL3  33_0402_5%  [R_0402]  19.2 85.87 0 top
RL4  0_0603_5%  [R0603_0OHM]  21.78 91.96 270 top
RL6  10K_0402_5%  [R_0402]  21.43 85 90 bottom
RL7  2.49K_0402_1%~D  [R_0402]  19.26 82.88 0 top
RL8  1K_0402_5%  [R_0402]  27.21 90.94 270 top
RL9  15K_0402_1%  [R_0402]  27.97 90.04 90 top
RL10  10K_0402_5%  [R_0402]  41.51 46.55 90 top
RL11  100K_0402_5%  [R_0402]  46.2 47.7 270 top
RL12  75_0603_5%  [R_0603]  18.51 77.15 270 bottom
RL13  75_0603_5%  [R_0603]  19.78 77.15 270 top
RL14  75_0603_5%  [R_0603]  18.51 77.15 270 top
RL15  75_0603_5%  [R_0603]  19.78 77.15 270 bottom
RL16  0_0402_5%  [R_0402]  29.52 90.61 90 top
RL17  0_0402_5%  [R0402_0OHM]  30.46 90.8 0 top
RPC1  1K_0804_8P4R_5%  [RP_0804_8P4R]  120.56 103.06 90 bottom
RPC2  100K_0804_8P4R_5%  [RP_0804_8P4R]  121.05 104.68 0 top
RPC3  1K_0804_8P4R_5%  [RP_0804_8P4R]  124.14 97.16 270 bottom
RPC4  33_0804_8P4R_5%  [RP_0804_8P4R]  61.12 37.98 0 bottom
RPC5  1K_0804_8P4R_5%  [RP_0804_8P4R]  65.13 39.48 180 bottom
RPC6  2.2K_0804_8P4R_5%  [RP_0804_8P4R]  119.47 62.64 0 top
RPC7  10K_0804_8P4R_5%  [RP_0804_8P4R]  131.23 57.82 90 top
RPH1  1K_0804_8P4R_5%  [RP_0804_8P4R]  83.74 124.59 270 bottom
RPH2  1K_0804_8P4R_5%  [RP_0804_8P4R]  95.61 124.65 270 bottom
RS3  4.7K_0402_5%  [R_0402]  183.55 35.63 270 top
RS4  4.7K_0402_5%  [R_0402]  191.3 43.06 270 top
RS5  0_0402_5%  [R0402_0OHM]  190.53 34.72 90 top
RS6  0_0402_5%  [R0402_0OHM]  183.04 44.97 270 top
RS7  4.7K_0402_5%  [R_0402]  189.65 34.72 90 top
RS8  4.7K_0402_5%  [R_0402]  186.98 34.72 90 top
RS9  4.7K_0402_5%  [R_0402]  185.33 34.72 90 top
RS10  4.7K_0402_5%  [R_0402]  187.49 44.97 270 top
RS11  4.7K_0402_5%  [R_0402]  183.93 44.97 270 top
RS12  4.7K_0402_5%  [R_0402]  186.6 44.97 270 top
RS13  4.7K_0402_5%  [R_0402]  185.71 44.05 90 top
RS14  4.7K_0402_5%  [R_0402]  192.05 38.79 0 top
RS15  4.7K_0402_5%  [R_0402]  192.05 39.68 0 top
RS16  4.99K_0402_1%  [R_0402]  182.67 35.62 180 top
RS17  4.7K_0402_5%  [R_0402]  192.24 43.11 0 top
RS18  4.7K_0402_5%  [R_0402]  187.87 35.63 270 top
RS19  4.7K_0402_5%  [R_0402]  188.38 44.05 90 top
RS20  4.7K_0402_5%  [R_0402]  188.76 35.63 270 top
RS21  4.7K_0402_5%  [R_0402]  184.82 44.05 90 top
RS23  0_0402_5%  [R0402_0OHM]  186.66 38.36 270 bottom
RS24  100K_0402_5%  [R_0402]  105.69 39.81 0 bottom
RS25  100K_0402_5%  [R_0402]  103.16 40.43 90 bottom
RS26  0_0402_5%  [R_0402]  42.25 26.79 0 bottom
RS27  0_0402_5%  [R0402_0OHM]  42.25 25.84 0 bottom
RS28  0_0402_5%  [R0402_0OHM]  31.66 25.97 90 top
RU1  0_0402_5%  [R_0402]  23.67 51.11 180 bottom
RU2  0_0402_5%  [R_0402]  23.67 50.1 180 bottom
RU3  0_0402_5%  [R_0402]  23.67 52 180 bottom
RU4  0_0402_5%  [R_0402]  23.67 52.89 180 bottom
RU5  0_0402_5%  [R_0402-NPM]  23.15 43.42 90 bottom
RU6  0_0402_5%  [R_0402-NPM]  23.91 43.42 90 bottom
RU7  0_0402_5%  [R_0402]  21.57 36.38 180 bottom
RU8  0_0402_5%  [R_0402]  21.57 37.14 180 bottom
RU9  0_0402_5%  [R_0402]  21.57 38.03 180 bottom
RU10  0_0402_5%  [R_0402]  21.57 38.79 180 bottom
RU11  0_0402_5%  [R_0402-NPM]  24.11 39.81 180 bottom
RU12  0_0402_5%  [R_0402-NPM]  24.11 40.57 180 bottom
RU13  0_0402_5%  [R_0402-NPM]  209.13 39.3 0 bottom
RU14  0_0402_5%  [R_0402-NPM]  209.13 38.54 0 bottom
RU15  0_0402_5%  [R_0402-NPM]  205.44 39.3 0 bottom
RU16  0_0402_5%  [R_0402-NPM]  205.44 38.54 0 bottom
RV1  100K_0402_5%  [R_0402]  212.43 53.91 0 top
RV2  100_0402_5%  [R_0402]  212.56 52 0 top
RV3  10K_0402_5%  [R_0402]  222.54 56.78 270 top
RV4  0_0402_5%  [R0402_0OHM]  222.46 58.48 0 top
RV5  0_0402_5%  [R_0402]  222.46 57.59 0 top
RV6  10K_0402_5%  [R_0402]  213.01 48.75 90 top
RV7  1M +-5% 0402  [R_0402]  127.55 106.27 180 top
RV8  0_0402_5%  [R0402_0OHM]  211.57 55.56 180 top
RV9  0_0805_5%  [R_0805]  203.53 53.4 0 bottom
RV10  0_0402_5%  [R_0402]  211.57 56.45 180 top
RV11  0_0402_5%  [R_0402-NPM]  19.67 100.24 180 top
RV12  150_0402_5%  [R_0402]  17.31 100.27 270 top
RV13  0_0402_5%  [R_0402-NPM]  19.67 99.37 180 top
RV14  0_0402_5%  [R_0402-NPM]  19.67 102.1 180 top
RV15  150_0402_5%  [R_0402]  17.31 102.05 270 top
RV16  499_0402_1%  [R_0402]  21.67 100.2 0 bottom
RV17  499_0402_1%  [R_0402]  21.67 99.31 0 bottom
RV18  499_0402_1%  [R_0402]  21.67 95.5 0 bottom
RV19  499_0402_1%  [R_0402]  21.67 96.39 0 bottom
RV20  499_0402_1%  [R_0402]  21.67 97.4 0 bottom
RV21  499_0402_1%  [R_0402]  21.67 98.29 0 bottom
RV22  0_0402_5%  [R_0402-NPM]  19.67 101.21 180 top
RV23  0_0402_5%  [R_0402-NPM]  19.67 98.34 180 top
RV24  150_0402_5%  [R_0402]  17.31 98.45 270 top
RV25  0_0402_5%  [R_0402-NPM]  19.67 97.48 180 top
RV26  0_0402_5%  [R_0402-NPM]  19.67 95.51 180 top
RV27  100K_0402_5%  [R_0402]  30.21 101.4 180 bottom
RV28  150_0402_5%  [R_0402]  17.31 95.56 90 top
RV29  0_0402_5%  [R_0402-NPM]  19.67 96.37 180 top
RV30  150K_0402_5%  [R_0402]  27.97 100.57 90 bottom
RV31  20K_0402_5%  [R_0402]  27.02 101.48 270 bottom
RV32  100K_0402_5%  [R_0402]  30.21 100.52 180 bottom
RV33  0_0402_5%  [R_0402]  49.95 88.95 90 top
RV34  499_0402_1%  [R_0402]  21.67 102.04 0 bottom
RV35  499_0402_1%  [R_0402]  21.67 101.15 0 bottom
RV36  2.2K_0402_5%  [R_0402]  26.95 95.41 90 top
RV37  2.2K_0402_5%  [R_0402]  26.15 95.41 90 top
RV38  2.2K_0402_5%  [R_0402]  25.15 95.41 90 top
RV39  2.2K_0402_5%  [R_0402]  24.35 95.41 90 top
RW2  0_0805_5%  [R_0805]  67.43 123.19 180 top
RW3  0_0402_5%  [R_0402]  71.01 133.56 0 top
RW4  0_0402_5%  [R0402_0OHM]  71.01 132.74 0 top
RW5  0_0402_5%  [R0402_0OHM]  78.71 132.89 90 top
RW6  0_0402_5%  [R_0402]  79.6 132.89 90 top
RW7  0_0402_5%  [R0402_0OHM]  71.93 130.61 180 top
RW8  0_0402_5%  [R0402_0OHM]  71.93 131.5 180 top
RW10  100K_0402_5%  [R_0402]  71.93 135.21 180 top
RW11  100K_0402_5%  [R_0402]  71.93 136.04 180 top
RW12  0_0402_5%  [R_0402]  71.93 134.39 180 top
RW13  0_0402_5%  [R_0402]  71.93 136.86 180 top
SW1  S TACT SW TST71A-N-220-S017 SPST H0  [SW_TST71-N-220-T170-S017_2P]  220.13 67.7 270 top
SW2  S TACT SW TST71A-N-220-S017 SPST H0  [SW_TST71-N-220-T170-S017_2P]  200.8 63.2 270 bottom
T1  -  [TPC12]  111.56 80.83 180 bottom
T2  -  [TPC12]  120.74 87.48 0 top
T3  -  [TPC12]  119.72 88.37 0 top
T4  -  [TPC12]  123.24 86.04 0 top
T5  -  [TPC12]  119.27 83.14 0 top
T6  -  [TPC12]  119.12 84.41 0 top
T7  -  [TPC12]  132.58 84.35 0 top
T8  -  [TPC12]  131.3 84.4 0 top
T9  -  [TPC12]  119.72 86.72 0 top
T10  -  [TPC12]  138.59 139.34 0 top
T11  -  [TPC12]  153.98 144.66 0 top
T12  -  [TPC12]  118.16 92.27 0 top
T13  -  [TPC12]  128.52 64.94 180 bottom
T14  -  [TPC12]  128.55 66.24 180 bottom
T15  -  [TPC12]  130.92 62.38 180 bottom
T16  -  [TPC12]  129.72 65.71 180 bottom
T17  -  [TPC12]  129.84 63.13 180 bottom
T18  -  [TPC12]  197.52 63.3 0 top
T19  PAD~D  [TPC12]  74.21 134.23 0 top
T23  PAD~D  [TPC12]  73.64 131.58 0 top
T24  PAD~D  [TPC12]  74.28 132.82 0 top
T25  -  [TPC12]  129.73 64.42 180 bottom
T26  -  [TPC12]  124.06 72.6 0 top
T27  -  [TPC12]  122.52 74.02 0 top
T28  -  [TPC12]  122.07 72.24 0 top
T29  -  [TPC12]  123.6 70.52 0 top
T30  -  [TPC12]  58.01 115.57 180 bottom
T31  -  [TPC12]  125.07 74.7 0 top
TL1  350UH_NS681611H  [BOTH_NS0014-LF_16P]  17.03 73.13 270 top
TL2  350UH_NS681611H  [BOTH_NS0014-LF_16P]  17.03 64.24 90 bottom
TP53  PAD  [TPC12]  21.07 86.84 0 top
TP54  PAD  [TPC12]  21.73 88.37 180 bottom
U1  G781-1P8F_MSOP8  [NCT7718W_MSOP8]  176.55 63.41 90 bottom
U2  EM5209VF DFN 14P DUAL LOAD SW  [TPS22966DPUR_SON14_2X3-S]  33.8 56.68 180 top
U3  EM5209VF DFN 14P DUAL LOAD SW  [TPS22966DPUR_SON14_2X3-S]  156.87 45.07 270 top
U4  EMB04N03G 1N SOP-8  [AO4430L_SO8]  153.45 61 180 bottom
U5  AS393MTR-G1 SOIC 8P  [LM393DR_SO8]  146.82 39.17 270 bottom
U6  EM5028V DFN 8P  [G2042RD1U_TDFN8_3X3]  124.13 40.93 0 bottom
UA1  -  [ALC3204-CG_MQFN40_5X5]  34.21 11.21 180 top
UC1  2D3201AJN23AC_BGA769~D  [2D3201AJN23AC_BGA_769P]  136.53 91.21 180 bottom
UC9  TC7SZ07FU_SSOP5  [SN74LVC1G07DCKR_SC70-5]  126.24 99.83 0 top
UC10  TC7SZ07FU_SSOP5  [SN74LVC1G07DCKR_SC70-5]  126.19 103.31 0 top
UC11  TC7SZ07FU_SSOP5  [SN74LVC1G07DCKR_SC70-5]  134.56 41.21 180 top
UC12  TC7SZ07FU_SSOP5  [SN74LVC1G07DCKR_SC70-5]  46.18 30.84 180 bottom
UC13  MC74VHC1G08DFT2G SC70 5P  [NC7SZ08P5X_NL_SC70-5]  98.33 46.73 0 top
UC14  -  [W25Q128FWSIQ_SO8]  122.83 47.54 90 bottom
UC15  -  [AP2138N-1P5TRG1_SOT23-3]  203.87 48.93 180 bottom
UE1  KB9542Q-E_LQFP128_14X14  [KB9542Q-B_LQFP128_14X14]  35.7 81.82 0 top
UL1  RTL8106E-CG_QFN32_4X4  [RTL8106E-CG_QFN32_4X4-S]  23.08 83.54 0 top
UL2  -  [SY6288C20AAC_SOT23-5]  42.65 49.14 270 top
US1  -  [PS8527CTQFN20GTR2A2_TQFN20_4X4]  185.59 40.81 0 top
US2  -  [LNG2DMTR_LGA12_2X2]  103.11 45.83 0 top
UU1  -  [SY6288D20AAC_SOT23-5]  19.15 38.23 0 top
UU2  -  [SY6288D20AAC_SOT23-5]  201.83 39.63 180 bottom
UV1  -  [SY6288C20AAC_SOT23-5]  219.18 55.76 0 top
UW1  -  [SY6288C20AAC_SOT23-5]  71.02 126.73 270 top
YC1  32.768KHZ 12.5PF 9H03200031  [Y_CM31532768DZFT_2P]  146.99 63.27 90 bottom
YC2  48MHZ 8PF +-20PPM 7V48000010  [Y_X3S048000D81H-W_4P]  144.28 90.25 270 bottom
YE1  32.768KHZ 7XZ3230001  [X_7XZ3200003_4P]  37.35 88.47 270 top
YL1  25MHZ_10PF_7V25000014  [Y_7V25000014_4P]  16.2 87.41 270 top

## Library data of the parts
C1 C2 C6-C8 C10 C13 C16 C17 C19 C20 C24 C25 C27 C31-C34 CA3 CA26-CA28 CA51-CA53 CA476 CA477 CA479-CA484 CA486 CA487 CA489 CA491 CA493-CA495 CA497-CA504 CC3 CC7 CC13 CC16 CC18 CC19 CC21 CC34-CC42 CC48 CC60-CC73 CC78 CC80 CC85-CC89 CC92-CC100 CC102-CC104 CC106 CC107 CC109-CC116 CC121 CD1-CD7 CD17-CD19 CD22-CD36 CD40 CD41 CD44 CE7-CE10 CE12 CE13 CH1 CH2 CL1 CL7 CL15 CL17 CL21 CS3-CS11 CS13-CS17 CS19 CS20 CS22 CS23 CS26 CS31-CS34 CU4 CU18 CV8 CV10 CV14 CV24 CW3 CW4 CW7 CW8 EC1 PC1-PC4 PC11-PC15 PC301 PC302 PC305-PC308 PC315 PC317 PC501 PC502 PC505-PC508 PC515-PC517 PC801-PC805 PC902 PC905 PC1805-PC1807 PC2503-PC2505 PCB01 PCB02 PCB03 PCB04 PCB05 PCB06 PCB08 PCB09-PCB19 PCB24-PCB28 PCB36 PCH01 PCH02 PCH09-PCH12 PCH14-PCH16 PCM01 PCM02 PCM11-PCM19 PCM22 PCM23 PCZ04 PCZ06 PCZ07 PCZ08 PCZ09-PCZ12 PCZ14 PCZ15 PCZ18 PCZ37 PCZ38 PCZ53 PCZ56-PCZ62 PCZ64-PCZ66 PCZ68 PCZ69 PCZ71-PCZ76 = C_0402
C3 C12 C28 C29 C36-C40 C43 C44 C53 CA25 CA496 CC23-CC33 CC51-CC59 CC74-CC77 CC79 CC120 CC122-CC127 CC129 CS27 CS28 CV1 CV9 PC303 PC304 PC309-PC314 PC316 PC503 PC504 PC509-PC514 PC518-PC520 PC1801-PC1804 PC2501 PC2502 PCB07 PCB20-PCB23 PCB29-PCB34 PCH03 PCH04 PCH05 PCH06 PCH07 PCH08 PCH13 PCH17-PCH20 PCM03 PCM04 PCM05 PCM06 PCM07 PCM08 PCM09 PCM10 PCM20 PCZ02 PCZ03 PCZ13 PCZ39 PCZ54 PCZ55 PCZ63 PCZ67 PCZ70 PCZ79 PCZ80 PCZ88 PCZ89 PCZ91-PCZ98 PCZ101-PCZ104 = C_0603
C4 C5 C9 C11 C14 C15 C18 C21-C23 C26 C30 C35 C41 C42 C45-C49 CA2 CA43-CA50 CA474 CA475 CA478 CA485 CA488 CA490 CA492 CA505 CA506 CC1 CC2 CC4-CC6 CC8-CC12 CC14 CC15 CC22 CC101 CC105 CC119 CC130 CD8-CD16 CD20 CD21 CD39 CD42 CD43 CE1-CE5 CE11 CE14-CE19 CL2-CL6 CL8-CL14 CL16 CL18 CL19 CS1 CS2 CS12 CS18 CS21 CS24 CS25 CS35 CU1 CU5 CU8 CU10-CU13 CU19-CU21 CU23-CU25 CV2-CV7 CV11-CV13 CV15-CV23 CW1 CW2 CW5 CW6 EC2 PC901 PC903 PC904 PC908-PC911 = C_0201
CD37 CD38 = C_D3
CL20 = C_1206
CLRP1 = SHORTPADS: User Part Number: PART#
CS29 CS30 CU2 CU3 CU7 CU15 CU17 CU22 = C_0805
D1 EU1 EU3 EU5 = AZC199-02SPR7G_SOT23-3
DA1 DA2 DA8 DA9 ED3 = L03ESDL5V0CC3-2_SOT23-3
DA5 DC3 DD1 DD2 = AZ5123-02SPR7G_SOT23-3
DA7 DV1 PD900 = BAT54CW_SOT323-3
DA10 = BAT54ATB_SOT523-3
DC1 EU2 PD1 = TVNST52302AB0_SOT523-3
DC2 DE1 DH1 DH2 PD501 PDM01 = RB751V-40_SOD323-2
DC4 = BAS40C_SOT23-3
DE2 = CK0402101V05_0402-2
ED1 ED2 PD5 PD6 = L03ESDL5V0CG3-2_SOT-523-3
EL1 EU4 EU6 = L05ESDL5V0NA-4_SLP2510P8-10-9
F1 F2 = F_T0603FF1000TM
F3 = F_MF-NSMF050-2
FD1-FD4 = FIDUCIAL_C40M80
FV1 = F_SMD1812P110TF-24
FV2 = F_1206L150PR
H1 H2 H4-H7 = H_3P0-G
H8 = H_3P3-G
H12 = H_3P2
H13 = H_3P0X4P0
H14 = H_5P6N
HCPU1-HCPU4 = H_3P9
J1 J4 J5 PJP302 PJP502 PJPH02 PJPM02 = JUMP_43X118
J2 J3 JP3-JP5 PJP801 PJP802 PJP1802 = JUMP_43X79
JDIMM1 = LOTES_ADDR0206-P001A02_260P
JEDP1 = ACES_51540-04001-P01_40P
JFAN1 JSPK1 = ACES_50224-00401-001_4P
JFP1 = ACES_51522-00801-001_8P
JHDD1 = ACES_51625-01201-001_12P
JHDMI1 = ACON_HMRF6-AK120C_19P-T
JHDT1 = SAMTE_ASP-136446-07-B_20P-T
JHP1 = YUQIU_PJ753-F07J1BE-B_7P-T
JIOB1 = ACES_51524-0160N-001_16P
JKB1 = HEFEN_AFB02-S30F1A-HF_30P-T
JKBBL1 = ACES_51575-00401-001_4P
JLAN1 = SINGA_2RJ3076-078211F_8P-T
JODD1 = ACES_50673-0120N-001_12P-T
JP2 JP6 PJP1801 PJP2501 PJP2502 PJPM03 = JUMP_43X39
JPWR1 = JXT_FP226H-004S1AM_4P
JRTC1 = LOTES_AAA-BAT-054-K01_2P
JSSD1 = LCN_DAN05-67306-0103_75P
JTP1 = ACES_51524-0080N-001_8P
JUSB1 JUSB2 = ACON_TARAN-9R1391_9P
JWLAN1 = LOTES_APCI0136-P001A_75P
L1 LU3 LU6-LU8 = INPAQ_MCM1012B900F06BP_4P
L5 LA15-LA18 = MURAT_BLM15PX221SN1D_2P
LA1 LA13 = MURAT_BLM15PX330SN1D_2P
LA2 LA3 PH1 PHZ1-PHZ4 PR1 PR3-PR7 PR9 PR31 PR33-PR45 PR302-PR304 PR306 PR504 PR506 PR508 PR509 PR802 PR803 PR901-PR909 PR911 PR1802 PR1803 PR1805 PR1806 PR2502-PR2504 PRB03 PRB04 PRB07 PRB08 PRB09-PRB13 PRB16-PRB18 PRB23-PRB28 PRB30 PRB35 PRB36 PRB38 PRB39 PRB42-PRB45 PRH02 PRH03 PRH04 PRH05 PRH06 PRH08 PRH09 PRH11-PRH13 PRM03 PRM06 PRM07 PRM10 PRM11 PRM13 PRZ00 PRZ02 PRZ03 PRZ04 PRZ05 PRZ07 PRZ09 PRZ11 PRZ13 PRZ15 PRZ16 PRZ18 PRZ21 PRZ23 PRZ47 PRZ51 PRZ65-PRZ67 PRZ70-PRZ73 PRZ76-PRZ81 PRZ85-PRZ87 R1-R4 R6 R17 R19 R21-R23 R25 R26 R28-R31 R33-R35 R37 R38 R40-R43 R45 R46 R49-R55 R57-R60 R63 R64 R68 R71-R73 R78 RA8 RA30-RA32 RA38-RA41 RA46-RA48 RA50-RA61 RC1 RC2 RC4-RC8 RC11 RC13-RC20 RC22-RC28 RC30-RC38 RC41-RC45 RC48-RC51 RC53 RC55-RC57 RC59-RC63 RC65 RC66 RC68-RC92 RC94-RC116 RC119-RC121 RC124-RC128 RC130-RC133 RD1-RD3 RD5 RD6 RE5 RE9-RE19 RE21 RE23-RE26 RE28 RE29 RE34 RE36 RE38 RE39 RE41 RE43 RE44 RE47 RE49-RE54 RH1-RH5 RL2 RL3 RL6-RL11 RL16 RS3 RS4 RS7-RS21 RS24-RS26 RU1-RU4 RU7-RU10 RV1-RV3 RV5-RV7 RV10 RV12 RV15-RV21 RV24 RV27 RV28 RV30-RV39 RW3 RW6 RW10-RW13 = R_0402
LC1 LC2 = KC_FBMA-L11-201209-121LMA50_2P
LE1 LE2 = MURAT_BLM15BD121SN1D_2P
LED1 = LED_LTW-295DSKS-5A_4P
LU1 LU2 LU4 LU5 = INPAQ_HCM1012GH900BP_4P-NPM
LV1 = TAI-T_HCB2012KF-221T30_2P
LV2-LV5 = INPAQ_HCM1012GH900BP_4P
PBATT1 = ACES_50458-01001-P01_10P-T
PCB70 = C_B2
PCZ00 PCZ77 PCZ78 PCZ86 PCZ87 = C_D2
PCZ90 = C_6P3X4P5
PD2 PD3 = BAV99W_SC70-3
PD14 PDB13 = PJSOT24C_SOT23-3
PD901 PD902 = RB520SM-30T2R_EMD2-2
PDB01 = LRB715FT1G_SOT323-3
PJP1-PJP3 PJP501 PJPZ01 = JUMP_43X79-NPM
PJP301 PJPH01 PJPM01 = JUMP_43X39-NPM
PJPB01 = JUMP_43X118-NPM
PJPDC1 = ACES_50458-00601-001_6P-T
PL1 PL2 PL4 PL511 PLB02 PLZ01 = 5A_Z150_1210_2P
PL3 = MURAT_BLM15AG102SN1D_2P
PL301 PL501 PLB01 PLH01 PLM01 = L_7X7X3_M_2P
PL311 PLH11 PLM11 = 5A_Z80_0805_2P
PL1811 = 5A_Z80_0805_2P-NPM
PL1812 = L_5X5X3_M_2P
PLZ02 PLZ04 = L_7X7X4_M_4P
PQ1 = FDV301N-G_SOT23-3
PQ2 = MMST3904-7-F_SOT323-3
PQ11 PQ801 PQB03 Q12 = 2N7002KW_SOT323-3
PQ12 = L2N7002DW1T1G_SC88-6
PQ13 = 2N7002KDW_SOT363-6
PQ900 = DMN65D8LDW-7_SOT363-6
PQB11 = EMB04N03H_EDFN5X6-8-5
PQB12 PQB13 = AON7506_DFN3X3-8-5
PQB25 PQB26 = AON7702L_DFN8-5
PQB28 = LMUN5113T1G_SOT323-3
PQB29 = LTC015EUBFS8TL_UMT3F
PQB31 = DMN65D8LW-7_SOT323-3
PQB32 PQB33 PQH01 = RUM002N02GT2L_VMT3
PQM01 = AONH36334_DFN3X3A8-10
PQZ01 PQZ04 = AON6380_DFN5X6-8-5
PQZ02 PQZ03 PQZ05 PQZ06 = Q_N_DFN56-8-5
PR32 PR305 PR505 PR1804 PRB15 PRB40 PRH07 PRM01 PRZ10 PRZ74 = R_1206
PR301 PR501 PRB14 R14 R47 RA34 RC118 RE8 RL4 = R0603_0OHM
PR502 PR503 PR507 PR801 PR1801 PR2501 PRB19-PRB22 PRB29 PRB31 PRB37 PRH01 PRH14 PRH15 PRH20 PRM08 PRM09 PRM14 PRZ06 PRZ69 PRZ75 R24 R36 R39 R44 R61 R65 RA33 RA35-RA37 RA62 RA65 RC3 RC9 RC10 RC12 RC21 RC29 RC39 RC40 RC52 RC54 RC67 RC93 RC122 RC123 RD4 RE6 RE20 RE30-RE33 RE35 RE37 RE48 RL17 RS5 RS6 RS23 RS27 RS28 RV4 RV8 RW4 RW5 RW7 RW8 = R0402_0OHM
PRB01 PRB02 = R_1206_4P-D
PRB41 PRM02 PRM04 PRM05 PRZ08 PRZ12 PRZ26 PRZ82 PRZ84 R7 R13 R20 R27 R32 R48 R56 RC117 RE2 RE3 RE7 RL1 RL12-RL15 = R_0603
PU301 = SY8286BRAC_QFN20_3X3
PU501 = SY8288CRAC_QFN20_3X3
PU800 = APL5336KAI-TRL_SOP8P8
PU900 = AZV3002RL-7_U-FLGA8_1P65X1P65
PU1801 = RT8061AZQW_WDFN10_3X3
PU2501 = RT9059GSP_SO8
PUB01 = ISL95522HRZ-T_TQFN32_4X4
PUH01 = RT6226AGQUF_UQFN12_3X3
PUM01 = RT8207PGQW_WQFN20_3X3
PUZ01 = ISL62771HRTZ-T_TQFN40_5X5-S
Q1 Q5 Q7 Q14 Q15 QC2 QS1 QV3 = DMN66D0LDW-7_SOT363-6
Q2 Q4 Q18-Q21 = AO3416_SOT23-3
Q3 Q6 Q8 Q9 Q11 Q16 Q17 QC3 QE1 QV1 = 2N7002K_SOT23-3
Q10 QA2 = LN2306LT1G_SOT23-3
Q13 = LMBT3904LT1G_SOT23-3
QC1 = MESS138W-G_SOT323-3
QV2 = MMBT3904_NL_SOT23-3
R5 R11 R12 R66 R67 = R_0201
R8 R9 RU5 RU6 RU11-RU16 RV11 RV13 RV14 RV22 RV23 RV25 RV26 RV29 = R_0402-NPM
RA1 = R0805_0OHM
RA63 RV9 RW2 = R_0805
RPC1-RPC7 RPH1 RPH2 = RP_0804_8P4R
SW1 SW2 = SW_TST71-N-220-T170-S017_2P
T1-T19 T23-T31 TP53 TP54 = TPC12
TL1 TL2 = BOTH_NS0014-LF_16P
U1 = NCT7718W_MSOP8
U2 U3 = TPS22966DPUR_SON14_2X3-S
U4 = AO4430L_SO8
U5 = LM393DR_SO8
U6 = G2042RD1U_TDFN8_3X3
UA1 = ALC3204-CG_MQFN40_5X5
UC1 = 2D3201AJN23AC_BGA_769P
UC9-UC12 = SN74LVC1G07DCKR_SC70-5
UC13 = NC7SZ08P5X_NL_SC70-5
UC14 = W25Q128FWSIQ_SO8
UC15 = AP2138N-1P5TRG1_SOT23-3
UE1 = KB9542Q-B_LQFP128_14X14
UL1 = RTL8106E-CG_QFN32_4X4-S
UL2 UV1 UW1 = SY6288C20AAC_SOT23-5
US1 = PS8527CTQFN20GTR2A2_TQFN20_4X4
US2 = LNG2DMTR_LGA12_2X2
UU1 UU2 = SY6288D20AAC_SOT23-5
YC1 = Y_CM31532768DZFT_2P
YC2 = Y_X3S048000D81H-W_4P
YE1 = X_7XZ3200003_4P
YL1 = Y_7V25000014_4P

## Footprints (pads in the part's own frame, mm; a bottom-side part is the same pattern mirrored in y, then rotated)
2D3201AJN23AC_BGA_769P
  round 0.406 smd: A2(0.6,0) A3(1.35,0) A39(21.25,0) A40(22,0) AA4(2.1,-11.3) AA5(2.9,-11.3) AA7(3.7,-11.3) AA8(4.5,-11.3) AA10(5.3,-11.3) AA11(6.3,-11.3) AA13(7.3,-11.3) AA15(8.3,-11.3) AA17(9.3,-11.3) AA19(10.3,-11.3) AA21(11.3,-11.3) AA23(12.3,-11.3) AA25(13.3,-11.3) AA27(14.3,-11.3) AA29(15.3,-11.3) AA31(16.3,-11.3) AA32(17.3,-11.3) AA34(18.1,-11.3) AA35(18.9,-11.3) AA37(19.7,-11.3) AA38(20.5,-11.3) AC4(2.1,-12.4) AC5(2.9,-12.4) AC7(3.7,-12.4) AC8(4.5,-12.4) AC10(5.3,-12.4) AC11(6.3,-12.3) AC13(7.3,-12.3) AC15(8.3,-12.3) AC17(9.3,-12.3) AC19(10.3,-12.3) AC21(11.3,-12.3) AC23(12.3,-12.3) AC25(13.3,-12.3) AC27(14.3,-12.3) AC29(15.3,-12.3) AC31(16.3,-12.3) AC32(17.3,-12.4) AC34(18.1,-12.4) AC35(18.9,-12.4) AC37(19.7,-12.4) AC38(20.5,-12.4) AE4(2.1,-13.5) AE5(2.9,-13.5) AE7(3.7,-13.5) AE8(4.5,-13.5) AE10(5.3,-13.5) AE11(6.3,-13.3) AE13(7.3,-13.3) AE15(8.3,-13.3) AE17(9.3,-13.3) AE19(10.3,-13.3) AE21(11.3,-13.3) AE23(12.3,-13.3) AE25(13.3,-13.3) AE27(14.3,-13.3) AE29(15.3,-13.3) AE31(16.3,-13.3) AE32(17.3,-13.5) AE34(18.1,-13.5) AE35(18.9,-13.5) AE37(19.7,-13.5) AE38(20.5,-13.5) AG4(2.1,-14.6) AG5(2.9,-14.6) AG7(3.7,-14.6) AG8(4.5,-14.6) AG10(5.3,-14.6) AG11(6.3,-14.3) AG13(7.3,-14.3) AG15(8.3,-14.3) AG17(9.3,-14.3) AG19(10.3,-14.3) AG21(11.3,-14.3) AG23(12.3,-14.3) AG25(13.3,-14.3) AG27(14.3,-14.3) AG29(15.3,-14.3) AG31(16.3,-14.3) AG32(17.3,-14.6) AG34(18.1,-14.6) AG35(18.9,-14.6) AG37(19.7,-14.6) AG38(20.5,-14.6) AJ4(2.1,-15.7) AJ5(2.9,-15.7) AJ7(3.7,-15.7) AJ8(4.5,-15.7) AJ10(5.3,-15.7) AJ11(6.3,-15.3) AJ13(7.3,-15.3) AJ15(8.3,-15.3) AJ17(9.3,-15.3) AJ19(10.3,-15.3) AJ21(11.3,-15.3) AJ23(12.3,-15.3) AJ25(13.3,-15.3) AJ27(14.3,-15.3) AJ29(15.3,-15.3) AJ31(16.3,-15.3) AJ32(17.3,-15.7) AJ34(18.1,-15.7) AJ35(18.9,-15.7) AJ37(19.7,-15.7) AJ38(20.5,-15.7) AL4(2.1,-16.8) AL5(2.9,-16.8) AL7(3.7,-16.8) AL8(4.5,-16.8) AL10(5.3,-16.8) AL11(6.3,-16.3) AL13(7.3,-16.3) AL15(8.3,-16.3) AL17(9.3,-16.3) AL19(10.3,-16.3) AL21(11.3,-16.3) AL23(12.3,-16.3) AL25(13.3,-16.3) AL27(14.3,-16.3) AL29(15.3,-16.3) AL31(16.3,-16.3) AL32(17.3,-16.8) AL34(18.1,-16.8) AL35(18.9,-16.8) AL37(19.7,-16.8) AL38(20.5,-16.8) AM11(5.8,-17.3) AM13(6.9,-17.3) AM15(8,-17.3) AM17(9.1,-17.3) AM19(10.2,-17.3) AM21(11.3,-17.3) AM23(12.4,-17.3) AM25(13.5,-17.3) AM27(14.6,-17.3) AM29(15.7,-17.3) AM31(16.8,-17.3) AN4(2.1,-17.9) AN5(2.9,-17.9) AN7(3.7,-17.9) AN8(4.5,-17.9) AN34(18.1,-17.9) AN35(18.9,-17.9) AN37(19.7,-17.9) AN38(20.5,-17.9) AP11(5.8,-18.1) AP13(6.9,-18.1) AP15(8,-18.1) AP17(9.1,-18.1) AP19(10.2,-18.1) AP21(11.3,-18.1) AP23(12.4,-18.1) AP25(13.5,-18.1) AP27(14.6,-18.1) AP29(15.7,-18.1) AP31(16.8,-18.1) AR4(2.1,-19) AR5(2.9,-19) AR7(3.7,-19) AR11(5.8,-18.9) AR13(6.9,-18.9) AR15(8,-18.9) AR17(9.1,-18.9) AR19(10.2,-18.9) AR21(11.3,-18.9) AR23(12.4,-18.9) AR25(13.5,-18.9) AR27(14.6,-18.9) AR29(15.7,-18.9) AR31(16.8,-18.9) AR35(18.9,-19) AR37(19.7,-19) AR38(20.5,-19) AU4(2.1,-20.1) AU7(3.6,-19.7) AU9(4.7,-19.7) AU11(5.8,-19.7) AU13(6.9,-19.7) AU15(8,-19.7) AU17(9.1,-19.7) AU19(10.2,-19.7) AU21(11.3,-19.7) AU23(12.4,-19.7) AU25(13.5,-19.7) AU27(14.6,-19.7) AU29(15.7,-19.7) AU31(16.8,-19.7) AU33(17.9,-19.7) AU35(19,-19.7) AU38(20.5,-20.1) AV7(3.6,-20.5) AV9(4.7,-20.5) AV11(5.8,-20.5) AV13(6.9,-20.5) AV15(8,-20.5) AV17(9.1,-20.5) AV19(10.2,-20.5) AV21(11.3,-20.5) AV23(12.4,-20.5) AV25(13.5,-20.5) AV27(14.6,-20.5) AV29(15.7,-20.5) AV31(16.8,-20.5) AV33(17.9,-20.5) AV35(19,-20.5) AW1(0,-21.25) AW41(22.6,-21.25) AY1(0,-22) AY2(0.7,-21.9) AY40(21.9,-21.9) AY41(22.6,-22) B1(0,-0.6) B2(0.7,-0.7) B40(21.9,-0.7) B41(22.6,-0.6) BA2(0.6,-22.6) BA3(1.35,-22.6) BA39(21.25,-22.6) BA40(22,-22.6) C1(0,-1.35) C41(22.6,-1.35) D7(3.6,-2.1) D9(4.7,-2.1) D11(5.8,-2.1) D13(6.9,-2.1) D15(8,-2.1) D17(9.1,-2.1) D19(10.2,-2.1) D21(11.3,-2.1) D23(12.4,-2.1) D25(13.5,-2.1) D27(14.6,-2.1) D29(15.7,-2.1) D31(16.8,-2.1) D33(17.9,-2.1) D35(19,-2.1) E4(2.1,-2.5) E7(3.6,-2.9) E9(4.7,-2.9) E11(5.8,-2.9) E13(6.9,-2.9) E15(8,-2.9) E17(9.1,-2.9) E19(10.2,-2.9) E21(11.3,-2.9) E23(12.4,-2.9) E25(13.5,-2.9) E27(14.6,-2.9) E29(15.7,-2.9) E31(16.8,-2.9) E33(17.9,-2.9) E35(19,-2.9) E38(20.5,-2.5) G4(2.1,-3.6) G5(2.9,-3.6) G7(3.7,-3.6) G11(5.8,-3.7) G13(6.9,-3.7) G15(8,-3.7) G17(9.1,-3.7) G19(10.2,-3.7) G21(11.3,-3.7) G23(12.4,-3.7) G25(13.5,-3.7) G27(14.6,-3.7) G29(15.7,-3.7) G31(16.8,-3.7) G35(18.9,-3.6) G37(19.7,-3.6) G38(20.5,-3.6) H11(5.8,-4.5) H13(6.9,-4.5) H15(8,-4.5) H17(9.1,-4.5) H19(10.2,-4.5) H21(11.3,-4.5) H23(12.4,-4.5) H25(13.5,-4.5) H27(14.6,-4.5) H29(15.7,-4.5) H31(16.8,-4.5) J4(2.1,-4.7) J5(2.9,-4.7) J7(3.7,-4.7) J8(4.5,-4.7) J34(18.1,-4.7) J35(18.9,-4.7) J37(19.7,-4.7) J38(20.5,-4.7) K11(5.8,-5.3) K13(6.9,-5.3) K15(8,-5.3) K17(9.1,-5.3) K19(10.2,-5.3) K21(11.3,-5.3) K23(12.4,-5.3) K25(13.5,-5.3) K27(14.6,-5.3) K29(15.7,-5.3) K31(16.8,-5.3) L4(2.1,-5.8) L5(2.9,-5.8) L7(3.7,-5.8) L8(4.5,-5.8) L10(5.3,-5.8) L11(6.3,-6.3) L13(7.3,-6.3) L15(8.3,-6.3) L17(9.3,-6.3) L19(10.3,-6.3) L21(11.3,-6.3) L23(12.3,-6.3) L25(13.3,-6.3) L27(14.3,-6.3) L29(15.3,-6.3) L31(16.3,-6.3) L32(17.3,-5.8) L34(18.1,-5.8) L35(18.9,-5.8) L37(19.7,-5.8) L38(20.5,-5.8) N4(2.1,-6.9) N5(2.9,-6.9) N7(3.7,-6.9) N8(4.5,-6.9) N10(5.3,-6.9) N11(6.3,-7.3) N13(7.3,-7.3) N15(8.3,-7.3) N17(9.3,-7.3) N19(10.3,-7.3) N21(11.3,-7.3) N23(12.3,-7.3) N25(13.3,-7.3) N27(14.3,-7.3) N29(15.3,-7.3) N31(16.3,-7.3) N32(17.3,-6.9) N34(18.1,-6.9) N35(18.9,-6.9) N37(19.7,-6.9) N38(20.5,-6.9) R4(2.1,-8) R5(2.9,-8) R7(3.7,-8) R8(4.5,-8) R10(5.3,-8) R11(6.3,-8.3) R13(7.3,-8.3) R15(8.3,-8.3) R17(9.3,-8.3) R19(10.3,-8.3) R21(11.3,-8.3) R23(12.3,-8.3) R25(13.3,-8.3) R27(14.3,-8.3) R29(15.3,-8.3) R31(16.3,-8.3) R32(17.3,-8) R34(18.1,-8) R35(18.9,-8) R37(19.7,-8) R38(20.5,-8) U4(2.1,-9.1) U5(2.9,-9.1) U7(3.7,-9.1) U8(4.5,-9.1) U10(5.3,-9.1) U11(6.3,-9.3) U13(7.3,-9.3) U15(8.3,-9.3) U17(9.3,-9.3) U19(10.3,-9.3) U21(11.3,-9.3) U23(12.3,-9.3) U25(13.3,-9.3) U27(14.3,-9.3) U29(15.3,-9.3) U31(16.3,-9.3) U32(17.3,-9.1) U34(18.1,-9.1) U35(18.9,-9.1) U37(19.7,-9.1) U38(20.5,-9.1) W4(2.1,-10.2) W5(2.9,-10.2) W7(3.7,-10.2) W8(4.5,-10.2) W10(5.3,-10.2) W11(6.3,-10.3) W13(7.3,-10.3) W15(8.3,-10.3) W17(9.3,-10.3) W19(10.3,-10.3) W21(11.3,-10.3) W23(12.3,-10.3) W25(13.3,-10.3) W27(14.3,-10.3) W29(15.3,-10.3) W31(16.3,-10.3) W32(17.3,-10.2) W34(18.1,-10.2) W35(18.9,-10.2) W37(19.7,-10.2) W38(20.5,-10.2)
  round 0.305 smd: A4(1.95,-0.35) A5(2.5,0) A6(3.05,-0.35) A7(3.6,0) A8(4.15,-0.35) A9(4.7,0) A10(5.25,-0.35) A11(5.8,0) A12(6.35,-0.35) A13(6.9,0) A14(7.45,-0.35) A15(8,0) A16(8.55,-0.35) A17(9.1,0) A18(9.65,-0.35) A19(10.2,0) A20(10.75,-0.35) A21(11.3,0) A22(11.85,-0.35) A23(12.4,0) A24(12.95,-0.35) A25(13.5,0) A26(14.05,-0.35) A27(14.6,0) A28(15.15,-0.35) A29(15.7,0) A30(16.25,-0.35) A31(16.8,0) A32(17.35,-0.35) A33(17.9,0) A34(18.45,-0.35) A35(19,0) A36(19.55,-0.35) A37(20.1,0) A38(20.65,-0.35) AA1(0,-11.3) AA2(0.7,-11.3) AA3(1.4,-11.3) AA39(21.2,-11.3) AA40(21.9,-11.3) AA41(22.6,-11.3) AB1(0.35,-11.85) AB2(1.05,-11.85) AB40(21.55,-11.85) AB41(22.25,-11.85) AC1(0,-12.4) AC2(0.7,-12.4) AC3(1.4,-12.4) AC39(21.2,-12.4) AC40(21.9,-12.4) AC41(22.6,-12.4) AD1(0.35,-12.95) AD2(1.05,-12.95) AD40(21.55,-12.95) AD41(22.25,-12.95) AE1(0,-13.5) AE2(0.7,-13.5) AE3(1.4,-13.5) AE39(21.2,-13.5) AE40(21.9,-13.5) AE41(22.6,-13.5) AF1(0.35,-14.05) AF2(1.05,-14.05) AF40(21.55,-14.05) AF41(22.25,-14.05) AG1(0,-14.6) AG2(0.7,-14.6) AG3(1.4,-14.6) AG39(21.2,-14.6) AG40(21.9,-14.6) AG41(22.6,-14.6) AH1(0.35,-15.15) AH2(1.05,-15.15) AH40(21.55,-15.15) AH41(22.25,-15.15) AJ1(0,-15.7) AJ2(0.7,-15.7) AJ3(1.4,-15.7) AJ39(21.2,-15.7) AJ40(21.9,-15.7) AJ41(22.6,-15.7) AK1(0.35,-16.25) AK2(1.05,-16.25) AK40(21.55,-16.25) AK41(22.25,-16.25) AL1(0,-16.8) AL2(0.7,-16.8) AL3(1.4,-16.8) AL39(21.2,-16.8) AL40(21.9,-16.8) AL41(22.6,-16.8) AM1(0.35,-17.35) AM2(1.05,-17.35) AM40(21.55,-17.35) AM41(22.25,-17.35) AN1(0,-17.9) AN2(0.7,-17.9) AN3(1.4,-17.9) AN39(21.2,-17.9) AN40(21.9,-17.9) AN41(22.6,-17.9) AP1(0.35,-18.45) AP2(1.05,-18.45) AP40(21.55,-18.45) AP41(22.25,-18.45) AR1(0,-19) AR2(0.7,-19) AR3(1.4,-19) AR39(21.2,-19) AR40(21.9,-19) AR41(22.6,-19) AT1(0.35,-19.55) AT2(1.05,-19.55) AT40(21.55,-19.55) AT41(22.25,-19.55) AU1(0,-20.1) AU2(0.7,-20.1) AU3(1.4,-20.1) AU39(21.2,-20.1) AU40(21.9,-20.1) AU41(22.6,-20.1) AV1(0.35,-20.65) AV2(1.05,-20.65) AV40(21.55,-20.65) AV41(22.25,-20.65) AW2(0.7,-21.2) AW3(1.4,-21.2) AW5(2.5,-21.2) AW7(3.6,-21.2) AW9(4.7,-21.2) AW11(5.8,-21.2) AW13(6.9,-21.2) AW15(8,-21.2) AW17(9.1,-21.2) AW19(10.2,-21.2) AW21(11.3,-21.2) AW23(12.4,-21.2) AW25(13.5,-21.2) AW27(14.6,-21.2) AW29(15.7,-21.2) AW31(16.8,-21.2) AW33(17.9,-21.2) AW35(19,-21.2) AW37(20.1,-21.2) AW39(21.2,-21.2) AW40(21.9,-21.2) AY3(1.4,-21.9) AY4(1.95,-21.55) AY5(2.5,-21.9) AY6(3.05,-21.55) AY7(3.6,-21.9) AY8(4.15,-21.55) AY9(4.7,-21.9) AY10(5.25,-21.55) AY11(5.8,-21.9) AY12(6.35,-21.55) AY13(6.9,-21.9) AY14(7.45,-21.55) AY15(8,-21.9) AY16(8.55,-21.55) AY17(9.1,-21.9) AY18(9.65,-21.55) AY19(10.2,-21.9) AY20(10.75,-21.55) AY21(11.3,-21.9) AY22(11.85,-21.55) AY23(12.4,-21.9) AY24(12.95,-21.55) AY25(13.5,-21.9) AY26(14.05,-21.55) AY27(14.6,-21.9) AY28(15.15,-21.55) AY29(15.7,-21.9) AY30(16.25,-21.55) AY31(16.8,-21.9) AY32(17.35,-21.55) AY33(17.9,-21.9) AY34(18.45,-21.55) AY35(19,-21.9) AY36(19.55,-21.55) AY37(20.1,-21.9) AY38(20.65,-21.55) AY39(21.2,-21.9) B3(1.4,-0.7) B4(1.95,-1.05) B5(2.5,-0.7) B6(3.05,-1.05) B7(3.6,-0.7) B8(4.15,-1.05) B9(4.7,-0.7) B10(5.25,-1.05) B11(5.8,-0.7) B12(6.35,-1.05) B13(6.9,-0.7) B14(7.45,-1.05) B15(8,-0.7) B16(8.55,-1.05) B17(9.1,-0.7) B18(9.65,-1.05) B19(10.2,-0.7) B20(10.75,-1.05) B21(11.3,-0.7) B22(11.85,-1.05) B23(12.4,-0.7) B24(12.95,-1.05) B25(13.5,-0.7) B26(14.05,-1.05) B27(14.6,-0.7) B28(15.15,-1.05) B29(15.7,-0.7) B30(16.25,-1.05) B31(16.8,-0.7) B32(17.35,-1.05) B33(17.9,-0.7) B34(18.45,-1.05) B35(19,-0.7) B36(19.55,-1.05) B37(20.1,-0.7) B38(20.65,-1.05) B39(21.2,-0.7) BA4(1.95,-22.25) BA5(2.5,-22.6) BA6(3.05,-22.25) BA7(3.6,-22.6) BA8(4.15,-22.25) BA9(4.7,-22.6) BA10(5.25,-22.25) BA11(5.8,-22.6) BA12(6.35,-22.25) BA13(6.9,-22.6) BA14(7.45,-22.25) BA15(8,-22.6) BA16(8.55,-22.25) BA17(9.1,-22.6) BA18(9.65,-22.25) BA19(10.2,-22.6) BA20(10.75,-22.25) BA21(11.3,-22.6) BA22(11.85,-22.25) BA23(12.4,-22.6) BA24(12.95,-22.25) BA25(13.5,-22.6) BA26(14.05,-22.25) BA27(14.6,-22.6) BA28(15.15,-22.25) BA29(15.7,-22.6) BA30(16.25,-22.25) BA31(16.8,-22.6) BA32(17.35,-22.25) BA33(17.9,-22.6) BA34(18.45,-22.25) BA35(19,-22.6) BA36(19.55,-22.25) BA37(20.1,-22.6) BA38(20.65,-22.25) C2(0.7,-1.4) C3(1.4,-1.4) C5(2.5,-1.4) C7(3.6,-1.4) C9(4.7,-1.4) C11(5.8,-1.4) C13(6.9,-1.4) C15(8,-1.4) C17(9.1,-1.4) C19(10.2,-1.4) C21(11.3,-1.4) C23(12.4,-1.4) C25(13.5,-1.4) C27(14.6,-1.4) C29(15.7,-1.4) C31(16.8,-1.4) C33(17.9,-1.4) C35(19,-1.4) C37(20.1,-1.4) C39(21.2,-1.4) C40(21.9,-1.4) D1(0.35,-1.95) D2(1.05,-1.95) D40(21.55,-1.95) D41(22.25,-1.95) E1(0,-2.5) E2(0.7,-2.5) E3(1.4,-2.5) E39(21.2,-2.5) E40(21.9,-2.5) E41(22.6,-2.5) F1(0.35,-3.05) F2(1.05,-3.05) F40(21.55,-3.05) F41(22.25,-3.05) G1(0,-3.6) G2(0.7,-3.6) G3(1.4,-3.6) G39(21.2,-3.6) G40(21.9,-3.6) G41(22.6,-3.6) H1(0.35,-4.15) H2(1.05,-4.15) H40(21.55,-4.15) H41(22.25,-4.15) J1(0,-4.7) J2(0.7,-4.7) J3(1.4,-4.7) J39(21.2,-4.7) J40(21.9,-4.7) J41(22.6,-4.7) K1(0.35,-5.25) K2(1.05,-5.25) K40(21.55,-5.25) K41(22.25,-5.25) L1(0,-5.8) L2(0.7,-5.8) L3(1.4,-5.8) L39(21.2,-5.8) L40(21.9,-5.8) L41(22.6,-5.8) M1(0.35,-6.35) M2(1.05,-6.35) M40(21.55,-6.35) M41(22.25,-6.35) N1(0,-6.9) N2(0.7,-6.9) N3(1.4,-6.9) N39(21.2,-6.9) N40(21.9,-6.9) N41(22.6,-6.9) P1(0.35,-7.45) P2(1.05,-7.45) P40(21.55,-7.45) P41(22.25,-7.45) R1(0,-8) R2(0.7,-8) R3(1.4,-8) R39(21.2,-8) R40(21.9,-8) R41(22.6,-8) T1(0.35,-8.55) T2(1.05,-8.55) T40(21.55,-8.55) T41(22.25,-8.55) U1(0,-9.1) U2(0.7,-9.1) U3(1.4,-9.1) U39(21.2,-9.1) U40(21.9,-9.1) U41(22.6,-9.1) V1(0.35,-9.65) V2(1.05,-9.65) V40(21.55,-9.65) V41(22.25,-9.65) W1(0,-10.2) W2(0.7,-10.2) W3(1.4,-10.2) W39(21.2,-10.2) W40(21.9,-10.2) W41(22.6,-10.2) Y1(0.35,-10.75) Y2(1.05,-10.75) Y40(21.55,-10.75) Y41(22.25,-10.75)
